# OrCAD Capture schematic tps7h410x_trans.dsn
size Custom
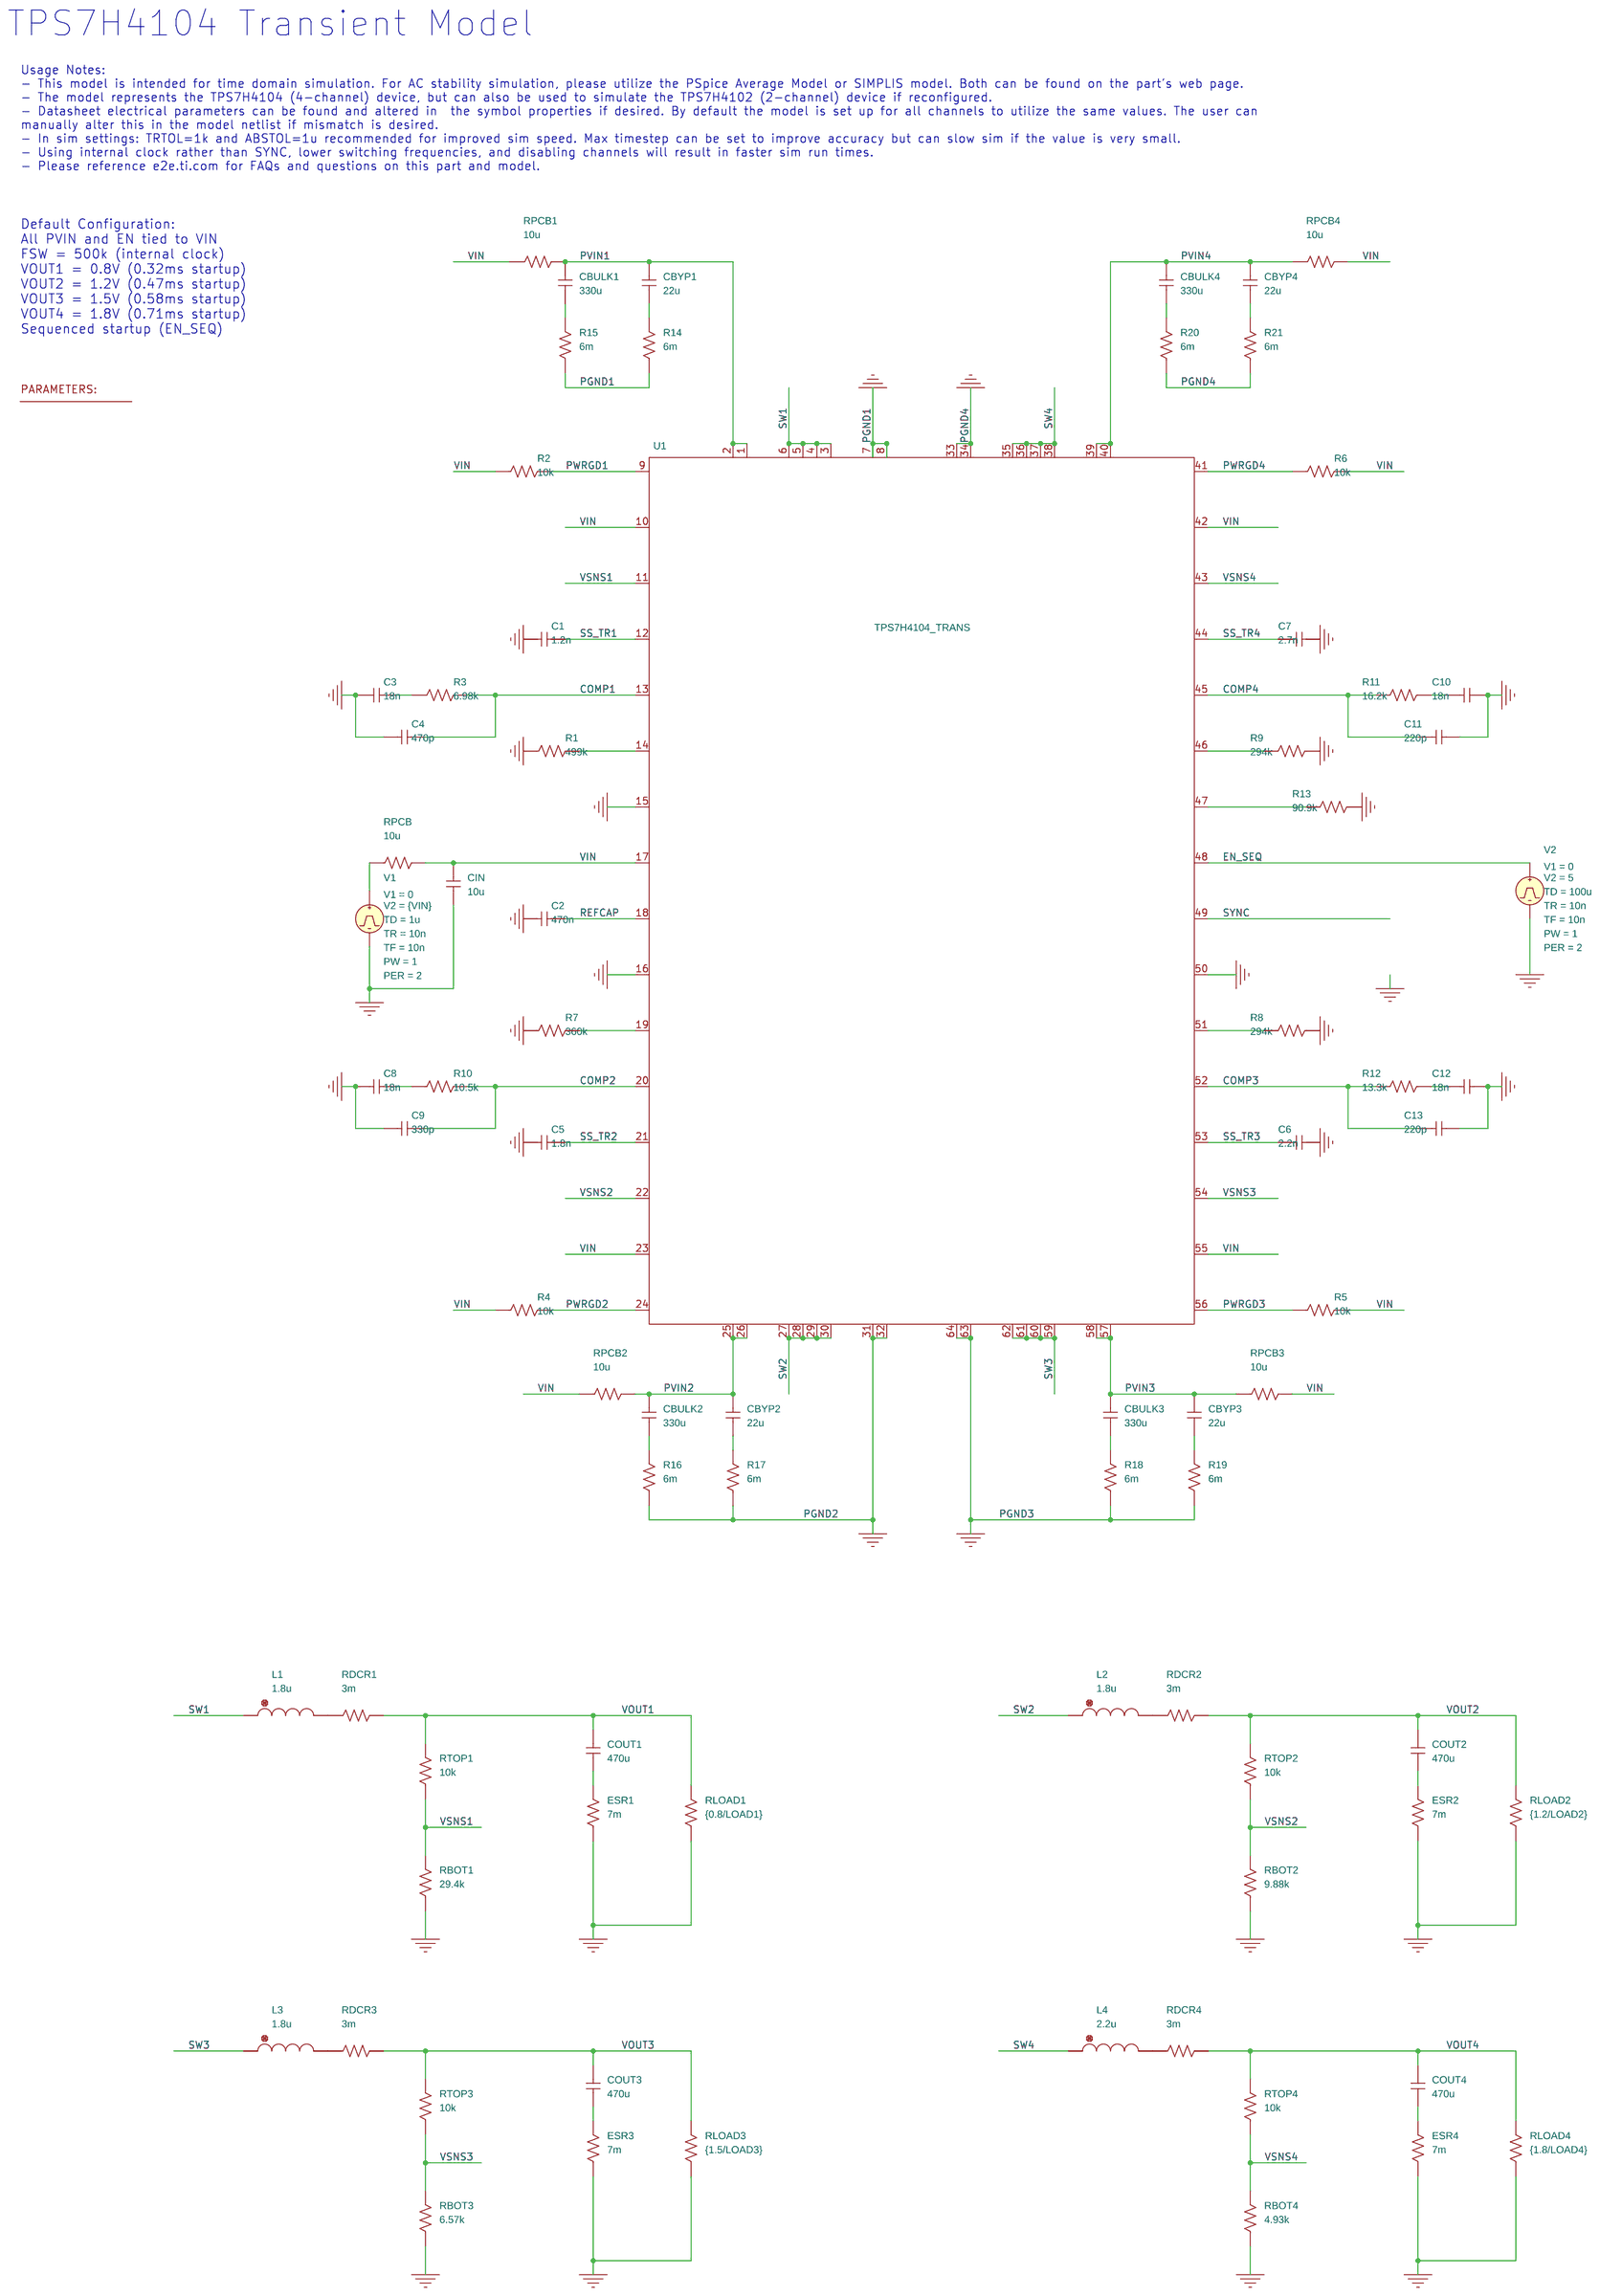
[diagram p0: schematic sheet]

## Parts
4  PARAM
C1  1.2n  [cap196]
C2  470n  [cap196]
C3  18n  [cap196]
C4  470p  [cap196]
C5  1.8n  [cap196]
C6  2.2n  [cap196]
C7  2.7n  [cap196]
C8  18n  [cap196]
C9  330p  [cap196]
C10  18n  [cap196]
C11  220p  [cap196]
C12  18n  [cap196]
C13  220p  [cap196]
CBULK1  330u  [cap196]
CBULK2  330u  [cap196]
CBULK3  330u  [cap196]
CBULK4  330u  [cap196]
CBYP1  22u  [cap196]
CBYP2  22u  [cap196]
CBYP3  22u  [cap196]
CBYP4  22u  [cap196]
CIN  10u  [cap196]
COUT1  470u  [cap196]
COUT2  470u  [cap196]
COUT3  470u  [cap196]
COUT4  470u  [cap196]
ESR1  7m  [AXRC05]
ESR2  7m  [AXRC05]
ESR3  7m  [AXRC05]
ESR4  7m  [AXRC05]
L1  1.8u  [DISC350x175LS200x100034]
L2  1.8u  [DISC350x175LS200x100034]
L3  1.8u  [DISC350x175LS200x100034]
L4  2.2u  [DISC350x175LS200x100034]
R1  499k  [AXRC05]
R2  10k  [AXRC05]
R3  6.98k  [AXRC05]
R4  10k  [AXRC05]
R5  10k  [AXRC05]
R6  10k  [AXRC05]
R7  360k  [AXRC05]
R8  294k  [AXRC05]
R9  294k  [AXRC05]
R10  10.5k  [AXRC05]
R11  16.2k  [AXRC05]
R12  13.3k  [AXRC05]
R13  90.9k  [AXRC05]
R14  6m  [AXRC05]
R15  6m  [AXRC05]
R16  6m  [AXRC05]
R17  6m  [AXRC05]
R18  6m  [AXRC05]
R19  6m  [AXRC05]
R20  6m  [AXRC05]
R21  6m  [AXRC05]
RBOT1  29.4k  [AXRC05]
RBOT2  9.88k  [AXRC05]
RBOT3  6.57k  [AXRC05]
RBOT4  4.93k  [AXRC05]
RDCR1  3m  [AXRC05]
RDCR2  3m  [AXRC05]
RDCR3  3m  [AXRC05]
RDCR4  3m  [AXRC05]
RLOAD1  {0.8/LOAD1}  [AXRC05]
RLOAD2  {1.2/LOAD2}  [AXRC05]
RLOAD3  {1.5/LOAD3}  [AXRC05]
RLOAD4  {1.8/LOAD4}  [AXRC05]
RPCB  10u  [AXRC05]
RPCB1  10u  [AXRC05]
RPCB2  10u  [AXRC05]
RPCB3  10u  [AXRC05]
RPCB4  10u  [AXRC05]
RTOP1  10k  [AXRC05]
RTOP2  10k  [AXRC05]
RTOP3  10k  [AXRC05]
RTOP4  10k  [AXRC05]
U1  TPS7H4104_TRANS
V1  VPULSE
V2  VPULSE

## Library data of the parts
4 = PARAM: LOAD1: 3; LOAD2: 3; LOAD3: 3; LOAD4: 3; VIN: 5
C1-C13 CBULK1-CBULK4 CBYP1-CBYP4 CIN COUT1-COUT4 = C
ESR1-ESR4 R1-R21 RBOT1-RBOT4 RDCR1-RDCR4 RLOAD1-RLOAD4 RPCB RPCB1-RPCB4 RTOP1-RTOP4 = R
L1-L4 = L: PSpiceTemplate: L^@REFDES %1 %2 ?TOLERANCE|L^@REFDES| @VALUE ?IC/IC=@IC/ ?TOLERANCE|\n.model l^@REFDES IND L=1 DEV=@TOLERANCE% TC1=@TC1 TC2=@TC2 IL1=@IL1 IL2=@IL2|
U1 = TPS7H4104_TRANS
V1 = VPULSE: PER: 2; PW: 1; TD: 1u; TF: 10n; TR: 10n; V1: 0; V2: {VIN}
V2 = VPULSE: PER: 2; PW: 1; TD: 100u; TF: 10n; TR: 10n; V1: 0; V2: 5

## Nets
PVIN1: CBULK1.1 CBYP1.1 RPCB1.2 U1.1 U1.2
PVIN2: CBULK2.1 CBYP2.1 RPCB2.2 U1.25 U1.26
PVIN3: CBULK3.1 CBYP3.1 RPCB3.1 U1.57 U1.58
PVIN4: CBULK4.1 CBYP4.1 RPCB4.1 U1.39 U1.40
VIN: CIN.1 R2.1 R4.1 R5.2 R6.2 RPCB.2 RPCB1.1 RPCB2.1 RPCB3.2 RPCB4.2 U1.10 U1.17 U1.23 U1.42 U1.55
0: C1.2 C2.2 C3.2 C4.2 C5.2 C6.2 C7.2 C8.2 C9.2 C10.2 C11.2 C12.2 C13.2 CIN.2 ESR1.1 ESR2.1 ESR3.1 ESR4.1 R1.1 R7.1 R8.1 R9.1 R13.1 R14.1 R15.1 R16.1 R17.1 R18.1 R19.1 R20.1 R21.1 RBOT1.1 RBOT2.1 RBOT3.1 RBOT4.1 RLOAD1.1 RLOAD2.1 RLOAD3.1 RLOAD4.1 U1.7 U1.8 U1.15 U1.16 U1.31 U1.32 U1.33 U1.34 U1.50 U1.63 U1.64 V1.2(-) V2.2(-)
COMP1: C4.1 R3.2 U1.13
COMP2: C9.1 R10.2 U1.20
COMP3: C13.1 R12.2 U1.52
COMP4: C11.1 R11.2 U1.45
EN_SEQ: U1.48 V2.1(+)
PWRGD1: R2.2 U1.9
PWRGD2: R4.2 U1.24
PWRGD3: R5.1 U1.56
PWRGD4: R6.1 U1.41
REFCAP: C2.1 U1.18
SS_TR1: C1.1 U1.12
SS_TR2: C5.1 U1.21
SS_TR3: C6.1 U1.53
SS_TR4: C7.1 U1.44
SW1: L1.1 U1.3 U1.4 U1.5 U1.6
SW2: L2.1 U1.27 U1.28 U1.29 U1.30
SW3: L3.1 U1.59 U1.60 U1.61 U1.62
SW4: L4.1 U1.35 U1.36 U1.37 U1.38
SYNC: U1.49
VOUT1: COUT1.1 RDCR1.2 RLOAD1.2 RTOP1.2
VOUT2: COUT2.1 RDCR2.2 RLOAD2.2 RTOP2.2
VOUT3: COUT3.1 RDCR3.2 RLOAD3.2 RTOP3.2
VOUT4: COUT4.1 RDCR4.2 RLOAD4.2 RTOP4.2
VSNS1: RBOT1.2 RTOP1.1 U1.11
VSNS2: RBOT2.2 RTOP2.1 U1.22
VSNS3: RBOT3.2 RTOP3.1 U1.54
VSNS4: RBOT4.2 RTOP4.1 U1.43
N16714976: CBULK1.2 R15.2
N16714982: CBYP1.2 R14.2
N16714988: CBULK4.2 R20.2
N16714994: CBYP4.2 R21.2
N16715832: C3.1 R3.1
N16715870: C10.1 R11.1
N16715992: R1.2 U1.14
N16715998: R9.2 U1.46
N16716046: R13.2 U1.47
N16716074: RPCB.1 V1.1(+)
N16716392: R7.2 U1.19
N16716398: R8.2 U1.51
N16716506: C8.1 R10.1
N16716544: C12.1 R12.1
N16717084: CBULK2.2 R16.2
N16717090: CBYP2.2 R17.2
N16717096: CBULK3.2 R18.2
N16717102: CBYP3.2 R19.2
N16718563: COUT1.2 ESR1.2
N16718569: COUT2.2 ESR2.2
N16719053: COUT3.2 ESR3.2
N16719059: COUT4.2 ESR4.2
N16730130: L1.2 RDCR1.1
N16730162: L4.2 RDCR4.1
N16730163: L2.2 RDCR2.1
N16730164: L3.2 RDCR3.1

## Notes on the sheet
- TPS7H4104 Transient Model
- Usage Notes:
  - This model is intended for time domain simulation. For AC stability simulation, please utilize the PSpice Average Model or SIMPLIS model. Both can be found on the part's web page.
  - The model represents the TPS7H4104 (4-channel) device, but can also be used to simulate the TPS7H4102 (2-channel) device if reconfigured.
  - Datasheet electrical parameters can be found and altered in  the symbol properties if desired. By default the model is set up for all channels to utilize the same values. The user can
  manually alter this in the model netlist if mismatch is desired.
  - In sim settings: TRTOL=1k and ABSTOL=1u recommended for improved sim speed. Max timestep can be set to improve accuracy but can slow sim if the value is very small.
  - Using internal clock rather than SYNC, lower switching frequencies, and disabling channels will result in faster sim run times.
  - Please reference e2e.ti.com for FAQs and questions on this part and model.
- Default Configuration:
  All PVIN and EN tied to VIN
  FSW = 500k (internal clock)
  VOUT1 = 0.8V (0.32ms startup)
  VOUT2 = 1.2V (0.47ms startup)
  VOUT3 = 1.5V (0.58ms startup)
  VOUT4 = 1.8V (0.71ms startup)
  Sequenced startup (EN_SEQ)
